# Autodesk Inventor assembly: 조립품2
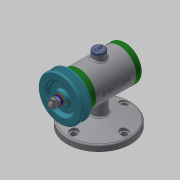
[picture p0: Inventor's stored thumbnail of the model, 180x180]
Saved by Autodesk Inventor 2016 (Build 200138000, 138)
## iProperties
Created: 2018-12
Part Number: 조립품2
Document SubType Name: Assembly
Designer: Administrator
Author: Administrator
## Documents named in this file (17)
- C:\Users\Administrator\Desktop\481208V1020\조립품2.iam
- C:\Users\Administrator\Desktop\481208V1020\본체.ipt
- C:\Users\Administrator\Desktop\481208V1020\베어링 15 x 32 x 9.ipt
- C:\Users\Administrator\Desktop\481208V1020\앞커버.ipt
- C:\Users\Administrator\Desktop\481208V1020\오일 실 15 25 7.ipt
- C:\Users\Administrator\Desktop\481208V1020\축.ipt
- C:\Users\Administrator\Desktop\481208V1020\볼트 M4 x 12.ipt
- C:\Users\Administrator\Desktop\481208V1020\V벨트풀리.ipt
- C:\Users\Administrator\Desktop\481208V1020\키 3 x 3 x 12.ipt
- C:\Users\Administrator\Desktop\481208V1020\너트 M8.ipt
- 너트 M8.ipt
- C:\Users\Administrator\Desktop\481208V1020\스프링와셔 8.ipt
- C:\Users\Administrator\Desktop\481208V1020\와셔 8x17.ipt
- C:\Users\Administrator\Desktop\481208V1020\고무캡.ipt
- C:\Users\Administrator\Desktop\481208V1020\뒤커버 - 복사본.ipt
- C:\Users\Administrator\Desktop\481208V1020\베어링 15 x 32 x 9 - 복사본.ipt
- C:\Users\Administrator\Desktop\481208V1020\볼트 M4 x 12 - 복사본.ipt
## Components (2 placed, 2 different names)
1. V벨트풀리:1
2. 고무캡:1
